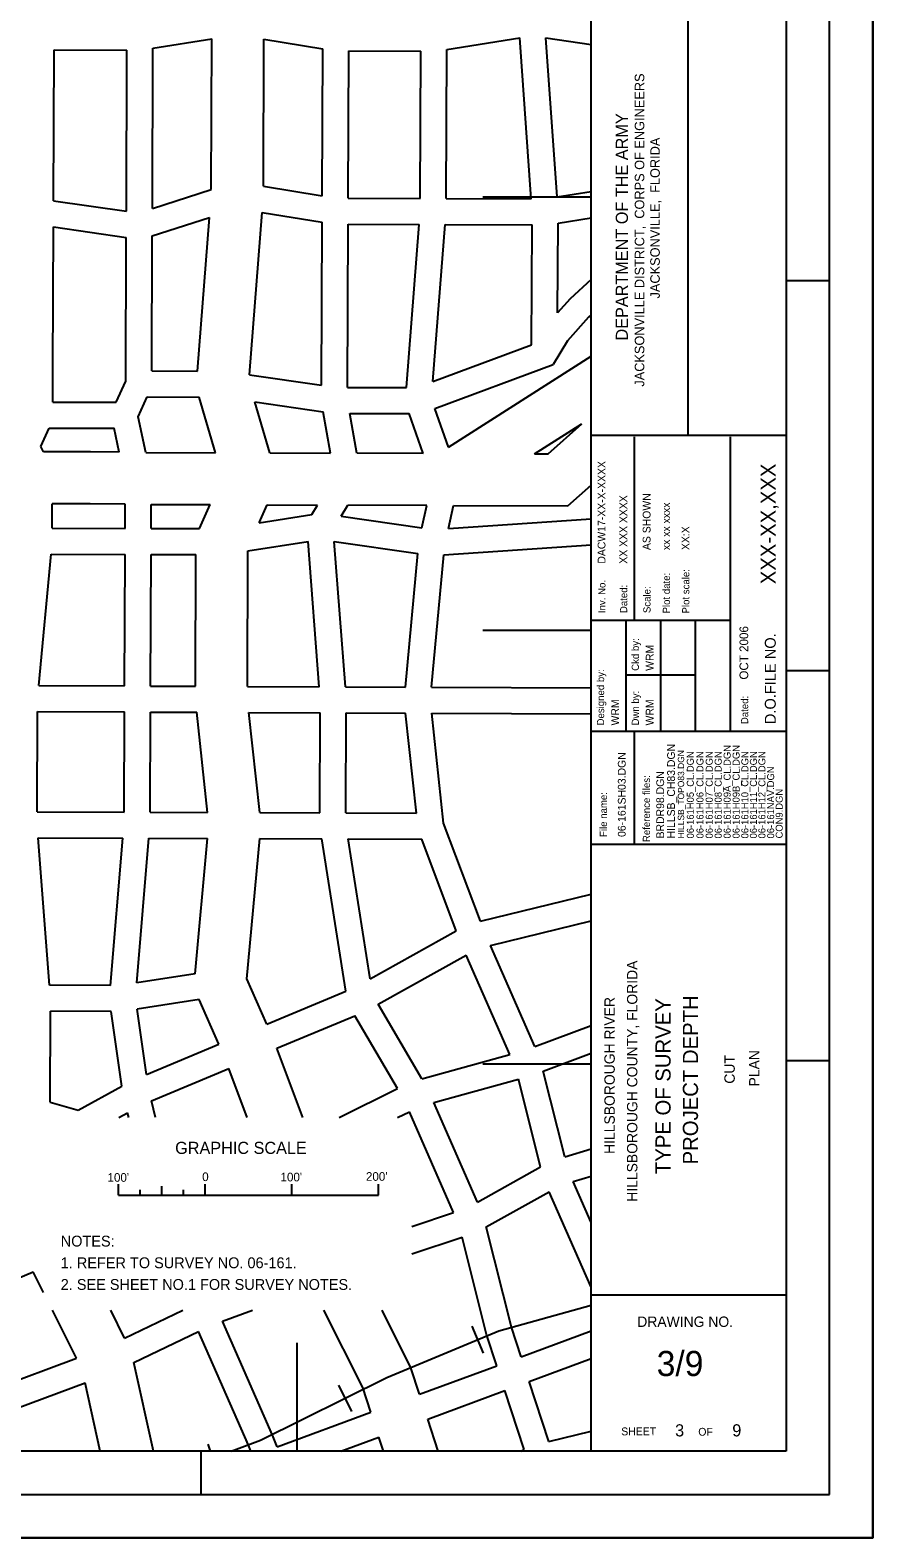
# Model space of a CAD drawing. Extents: x 501128 to 509328, y 1314906 to 1320706.
# Drawn here: x 507384 to 509328, y 1314906 to 1318384 of the extents above; entities that cross this region are included whole.
import ezdxf

# ---------------------------------------------------------------- set-up
doc = ezdxf.new("R2010")
doc.units = 0
for name, color, linetype in [('G-ANNO-TEXT', 7, 'Continuous'), ('G-ANNO-TTLB', 7, 'Continuous'), ('Level 1', 7, 'Continuous'), ('Level 14', 7, 'Continuous'), ('Level 2', 7, 'Continuous'), ('Level 32', 7, 'Continuous'), ('Level 37', 7, 'Continuous'), ('Level 5', 7, 'Continuous'), ('Level 6', 7, 'Continuous')]:
    doc.layers.add(name, color=color, linetype=linetype)

msp = doc.modelspace()

# ---------------------------------------------------------------- linework, layer by layer
at = {"layer": 'G-ANNO-TTLB'}
for p, q in [((509228.1, 1315006.3), (509228.1, 1320606.3)), ((508678.1, 1315106.3), (508678.1, 1320506.3)), ((509128.1, 1320506.3), (509128.1, 1315106.3)), ((508901.5, 1318488.9), (508901.5, 1317449.1)), ((509228.1, 1317806.3), (509128.1, 1317806.3)), ((509128.1, 1317449.1), (508678.1, 1317449.1)), ((508777.7, 1317446.3), (508777.7, 1317022.5)), ((508998.5, 1317446.3), (508998.5, 1316766.3)), ((508998.5, 1317022.5), (508678.1, 1317022.5)), ((508758.3, 1317022.5), (508758.3, 1316766.3)), ((508838.1, 1317022.5), (508838.1, 1316766.3)), ((508918.5, 1317022.5), (508918.5, 1316766.3)), ((508918.5, 1316896.7), (508758.3, 1316896.7)), ((509228.1, 1316906.3), (509128.1, 1316906.3)), ((509128.1, 1316766.3), (508678.1, 1316766.3)), ((508777.7, 1316766.3), (508777.7, 1316506.1)), ((509128.1, 1316506.1), (508678.1, 1316506.1)), ((509228.1, 1316006.3), (509128.1, 1316006.3)), ((509128.1, 1315466.3), (508678.1, 1315466.3)), ((509128.1, 1315106.3), (501478.1, 1315106.3)), ((507778.1, 1315006.3), (507778.1, 1315106.3)), ((501228.1, 1315006.3), (509228.1, 1315006.3))]:
    msp.add_line(p, q, dxfattribs=at)
for points in [[(501128.1, 1314906.3), (509328.1, 1314906.3), (509328.1, 1320706.3), (501128.1, 1320706.3)], [(501128.1, 1314906.3), (509328.1, 1314906.3), (509328.1, 1320706.3), (501128.1, 1320706.3)], [(501128.1, 1320706.3), (509328.1, 1320706.3), (509328.1, 1314906.3), (501128.1, 1314906.3)]]:
    msp.add_lwpolyline(points, close=True, dxfattribs=at)
msp.add_lwpolyline([(509278.1, 1314906.3), (509328.1, 1314906.3), (509328.1, 1314956.3)], dxfattribs=at)
at = {"layer": 'Level 1'}
for p, q in [((507587.2, 1315697.1), (507587.2, 1315722.2)), ((507687.2, 1315697.1), (507687.2, 1315717.6)), ((507787.2, 1315697.1), (507787.2, 1315722.2)), ((507787.2, 1315697.1), (507787.2, 1315722.2)), ((507987.2, 1315697.1), (507987.2, 1315722.2)), ((508187.2, 1315697.1), (508187.2, 1315722.2)), ((507587.2, 1315697.1), (508187.3, 1315697.1)), ((507637.2, 1315697.6), (507637.2, 1315709.1)), ((507687.2, 1315697.6), (507687.2, 1315709.1)), ((507737.2, 1315697.6), (507737.2, 1315709.1)), ((507787.2, 1315697.1), (507787.2, 1315709.1))]:
    msp.add_line(p, q, dxfattribs=at)
at = {"layer": 'Level 14'}
for p, q in [((507801.6, 1318016.3), (507803, 1318363.9)), ((507921.7, 1318024.3), (507922.9, 1318363.5)), ((507437.3, 1317990.9), (507438.6, 1318339)), ((507769.8, 1317597.9), (507797.4, 1317952)), ((507889.5, 1317589.1), (507918.7, 1317964)), ((507435.9, 1317605.5), (507437.1, 1317930.3)), ((508348.9, 1317422.4), (508678.1, 1317632.5)), ((507435.6, 1317526.4), (507435.9, 1317605.5)), ((507811.3, 1317409.6), (507773.9, 1317537.9)), ((507936.5, 1317409.1), (507902.2, 1317526.6)), ((507408.5, 1317423.8), (507427.7, 1317466.5)), ((508547.7, 1317406.9), (508656.9, 1317476.5)), ((507414.1, 1317411.3), (507408.5, 1317423.8)), ((507650.8, 1317410.2), (507811.3, 1317409.6)), ((507936.5, 1317409.1), (508076.5, 1317408.6)), ((508290.5, 1317407.8), (508137.4, 1317408.4)), ((507434.5, 1317235.6), (507434.7, 1317291.3)), ((507662.9, 1317290.2), (507798.9, 1317289.7)), ((507774.1, 1317234.3), (507798.9, 1317289.7)), ((507911.7, 1317247.9), (507930.2, 1317289.2)), ((507930.2, 1317289.2), (508046.8, 1317288.7)), ((508299.1, 1317287.8), (508116.5, 1317288.5)), ((507403.7, 1316872.2), (507431.8, 1317175.6)), ((507765.1, 1316870.8), (507766.2, 1317174.4)), ((507885.1, 1316870.4), (507886.2, 1317183.2)), ((507399.7, 1316581.3), (507400.6, 1316812.2)), ((507792.5, 1316579.9), (507767.8, 1316810.8)), ((507913.3, 1316579.4), (507888.5, 1316810.3)), ((507428.3, 1316181.3), (507402.1, 1316521.3)), ((507764.2, 1316207.4), (507793.1, 1316519.9)), ((507883.7, 1316196.1), (507913.6, 1316519.4)), ((507929.8, 1316091.1), (507883.7, 1316196.1)), ((507819.1, 1316044.9), (507773.7, 1316148.2)), ((507429.5, 1315911.1), (507430.3, 1316121.3)), ((508012.6, 1315875.7), (507952.5, 1316035.6)), ((507884.4, 1315875.7), (507841.7, 1315989.3)), ((507414.6, 1315472.1), (507390.8, 1315519.6)), ((507490.8, 1315320.6), (507435.1, 1315431.3)), ((507601.6, 1315367.3), (507569.4, 1315431.3)), ((508150.9, 1315252.9), (508061.2, 1315431.3)), ((508262.1, 1315298.8), (508195.5, 1315431.3)), ((507667.8, 1315106.3), (507623.1, 1315311.1)), ((508282.2, 1315237.4), (508262.1, 1315298.8)), ((507544.9, 1315106.3), (507510.6, 1315264)), ((508169.5, 1315195.9), (508150.9, 1315252.9)), ((508325.3, 1315106.3), (508300.9, 1315180.4)), ((508199, 1315106.3), (508188.3, 1315138.8))]:
    msp.add_line(p, q, dxfattribs=at)
for points in [[(508547.7, 1317406.9), (508578.8, 1317406.7), (508656.9, 1317476.5)], [(507589.3, 1317410.7), (507522.5, 1317411.3), (507414.1, 1317411.3)], [(508360.6, 1317287.6), (508624.5, 1317286.6), (508678.1, 1317334.6)], [(507602.9, 1317290.5), (507522, 1317291.3), (507434.7, 1317291.3)]]:
    msp.add_lwpolyline(points, dxfattribs=at)
at = {"layer": 'Level 2'}
for p, q in [((508428.1, 1318000), (508678.1, 1318000)), ((508428.1, 1317000), (508678.1, 1317000)), ((508428.1, 1316000), (508678.1, 1316000)), ((508000, 1315106.3), (508000, 1315356.3))]:
    msp.add_line(p, q, dxfattribs=at)
at = {"layer": 'Level 32'}
for p, q in [((507666.9, 1318342.6), (507803, 1318363.9)), ((507922.9, 1318363.5), (508058.8, 1318341.1)), ((508344.8, 1318340), (508513.4, 1318366.5)), ((508539.5, 1317994.9), (508513.4, 1318366.5)), ((508599.3, 1317999.5), (508573.6, 1318366.2)), ((508573.6, 1318366.2), (508678.1, 1318351.1)), ((507438.6, 1318339), (507606.9, 1318338.3)), ((507605.5, 1317966.6), (507606.9, 1318338.3)), ((507665.5, 1317973), (507666.9, 1318342.6)), ((508057.6, 1318001.9), (508058.8, 1318341.1)), ((508117.5, 1317996.5), (508118.8, 1318336.4)), ((508118.8, 1318336.4), (508284.8, 1318335.8)), ((508283.5, 1317995.9), (508284.8, 1318335.8)), ((508343.5, 1317995.7), (508344.8, 1318340)), ((507665.5, 1317973), (507801.6, 1318016.3)), ((507921.7, 1318024.3), (508057.6, 1318001.9)), ((508599.3, 1317999.5), (508678.1, 1318011.9)), ((507437.3, 1317990.9), (507605.5, 1317966.6)), ((508117.5, 1317996.5), (508283.5, 1317995.9)), ((508343.5, 1317995.7), (508539.5, 1317994.9)), ((507665.3, 1317910), (507797.4, 1317952)), ((507918.7, 1317964), (508057.3, 1317941.2)), ((508055.9, 1317565), (508057.3, 1317941.2)), ((508601.6, 1317939.1), (508678.1, 1317951.2)), ((507437.1, 1317930.3), (507605.2, 1317906)), ((507604, 1317574.9), (507605.2, 1317906)), ((507664.1, 1317598.3), (507665.3, 1317910)), ((508115.9, 1317560.3), (508117.3, 1317936.5)), ((508117.3, 1317936.5), (508281, 1317935.9)), ((508251.7, 1317559.7), (508281, 1317935.9)), ((508313, 1317574.1), (508341.2, 1317935.7)), ((508341.2, 1317935.7), (508541.6, 1317934.9)), ((508540.5, 1317658.5), (508541.6, 1317934.9)), ((508600.8, 1317732.5), (508601.6, 1317939.1)), ((508313, 1317574.1), (508540.5, 1317658.5)), ((507664.1, 1317598.3), (507769.8, 1317597.9)), ((508317.6, 1317511.8), (508590.8, 1317613.2)), ((507582, 1317525.9), (507604, 1317574.9)), ((507889.5, 1317589.1), (508055.9, 1317565)), ((508115.9, 1317560.3), (508251.7, 1317559.7)), ((507435.6, 1317526.4), (507582, 1317525.9)), ((507632.8, 1317492.6), (507653.4, 1317538.3)), ((507653.4, 1317538.3), (507773.9, 1317537.9)), ((507902.2, 1317526.6), (508060, 1317503.8)), ((507650.8, 1317410.2), (507632.8, 1317492.6)), ((508076.5, 1317408.6), (508060, 1317503.8)), ((508137.4, 1317408.4), (508121.5, 1317500.2)), ((508121.5, 1317500.2), (508258.2, 1317499.7)), ((508290.5, 1317407.8), (508258.2, 1317499.7)), ((508348.9, 1317422.4), (508317.6, 1317511.8)), ((507427.7, 1317466.5), (507577.2, 1317465.9)), ((507589.3, 1317410.7), (507577.2, 1317465.9)), ((507602.7, 1317235), (507602.9, 1317290.5)), ((507662.7, 1317234.8), (507662.9, 1317290.2)), ((508033.9, 1317267.1), (508046.8, 1317288.7)), ((508101.2, 1317262.9), (508116.5, 1317288.5)), ((508287.4, 1317236), (508299.1, 1317287.8)), ((508348.7, 1317234.9), (508360.6, 1317287.6)), ((507911.7, 1317247.9), (508033.9, 1317267.1)), ((508101.2, 1317262.9), (508287.4, 1317236)), ((508348.7, 1317234.9), (508678.1, 1317256.9)), ((507434.5, 1317235.6), (507602.7, 1317235)), ((507662.7, 1317234.8), (507774.1, 1317234.3)), ((507431.8, 1317175.6), (507602.5, 1317175)), ((507601.4, 1316871.4), (507602.5, 1317175)), ((507661.4, 1316871.2), (507662.5, 1317174.8)), ((507662.5, 1317174.8), (507766.2, 1317174.4)), ((507886.2, 1317183.2), (508025, 1317205)), ((508050.8, 1316869.7), (508025, 1317205)), ((508111, 1316869.5), (508085.2, 1317204.6)), ((508085.2, 1317204.6), (508278.1, 1317176.7)), ((508249.6, 1316869), (508278.1, 1317176.7)), ((508338.1, 1317174.1), (508678.1, 1317196.8)), ((508309.8, 1316868.8), (508338.1, 1317174.1)), ((507403.7, 1316872.2), (507601.4, 1316871.4)), ((507661.4, 1316871.2), (507765.1, 1316870.8)), ((507885.1, 1316870.4), (508050.8, 1316869.7)), ((508111, 1316869.5), (508249.6, 1316869)), ((508309.8, 1316868.8), (508678.1, 1316867.4)), ((507400.6, 1316812.2), (507601.1, 1316811.4)), ((507600.3, 1316580.6), (507601.1, 1316811.4)), ((507660.3, 1316580.4), (507661.1, 1316811.2)), ((507661.1, 1316811.2), (507767.8, 1316810.8)), ((507888.5, 1316810.3), (508053.1, 1316809.7)), ((508052.2, 1316578.9), (508053.1, 1316809.7)), ((508112.2, 1316578.7), (508113.1, 1316809.5)), ((508113.1, 1316809.5), (508249.9, 1316809)), ((508274.7, 1316578.1), (508249.9, 1316809)), ((508337.5, 1316554.9), (508310.3, 1316808.8)), ((508310.3, 1316808.8), (508678.1, 1316807.4)), ((507399.7, 1316581.3), (507600.3, 1316580.6)), ((507660.3, 1316580.4), (507792.5, 1316579.9)), ((507913.3, 1316579.4), (508052.2, 1316578.9)), ((508112.2, 1316578.7), (508274.7, 1316578.1)), ((508422.7, 1316328.6), (508337.5, 1316554.9)), ((507402.1, 1316521.3), (507597.5, 1316520.6)), ((507568.8, 1316180.8), (507597.5, 1316520.6)), ((507629.5, 1316186.3), (507657.7, 1316520.4)), ((507657.7, 1316520.4), (507793.1, 1316519.9)), ((507913.6, 1316519.4), (508056.5, 1316518.9)), ((508111.9, 1316167.2), (508056.5, 1316518.9)), ((508168.1, 1316195.8), (508117.2, 1316518.6)), ((508117.2, 1316518.6), (508287.3, 1316518)), ((508366.8, 1316306.7), (508287.3, 1316518)), ((508422.7, 1316328.6), (508678.1, 1316391.5)), ((508168.1, 1316195.8), (508366.8, 1316306.7)), ((508445.8, 1316272.5), (508678.1, 1316329.7)), ((508548.1, 1316039.7), (508445.8, 1316272.5)), ((508186.6, 1316137.4), (508389.8, 1316250.8)), ((508490.6, 1316021.4), (508389.8, 1316250.8)), ((507764.2, 1316207.4), (507629.5, 1316186.3)), ((507568.8, 1316180.8), (507428.3, 1316181.3)), ((507929.8, 1316091.1), (508111.9, 1316167.2)), ((507773.7, 1316148.2), (507630.3, 1316125.6)), ((508287.7, 1315965.1), (508186.6, 1316137.4)), ((507570.4, 1316120.8), (507430.3, 1316121.3)), ((507595.2, 1315948.6), (507570.4, 1316120.8)), ((507652, 1315975.1), (507630.3, 1316125.6)), ((507952.5, 1316035.6), (508132.6, 1316110.8)), ((508231.3, 1315942.6), (508132.6, 1316110.8)), ((508548.1, 1316039.7), (508678.1, 1316088)), ((507652, 1315975.1), (507819.1, 1316044.9)), ((508287.7, 1315965.1), (508490.6, 1316021.4)), ((508567.7, 1315983), (508678.1, 1316024)), ((507663.2, 1315914.7), (507841.7, 1315989.3)), ((508314.9, 1315910.4), (508510.4, 1315964.6)), ((508561, 1315762), (508510.4, 1315964.6)), ((508617.1, 1315784.9), (508567.7, 1315983)), ((507494.7, 1315892.5), (507595.2, 1315948.6)), ((508096.5, 1315875.7), (508231.3, 1315942.6)), ((507429.5, 1315911.1), (507494.7, 1315892.5)), ((507672.9, 1315875.7), (507663.2, 1315914.7)), ((508231.6, 1315875.7), (508258.7, 1315889.2)), ((508360.8, 1315656.7), (508258.7, 1315889.2)), ((508415.7, 1315681), (508314.9, 1315910.4)), ((507587.8, 1315875.7), (507608.2, 1315887.1)), ((507611.1, 1315875.7), (507608.2, 1315887.1)), ((508617.1, 1315784.9), (508678.1, 1315803.4)), ((508415.7, 1315681), (508561, 1315762)), ((508636.7, 1315728.1), (508678.1, 1315740.7)), ((508678.1, 1315633.9), (508636.7, 1315728.1)), ((508436.2, 1315623.7), (508581.5, 1315704.8)), ((508678.1, 1315484.8), (508581.5, 1315704.8)), ((508264.3, 1315624.5), (508360.8, 1315656.7)), ((508494, 1315392.3), (508436.2, 1315623.7)), ((508264.3, 1315561.3), (508380.3, 1315600)), ((508436.3, 1315375.6), (508380.3, 1315600)), ((507221.6, 1315448.9), (507390.8, 1315519.6)), ((507601.6, 1315367.3), (507735.5, 1315431.3)), ((507827.6, 1315405.8), (507896.4, 1315431.3)), ((507943.1, 1315142.9), (507827.6, 1315405.8)), ((507623.1, 1315311.1), (507772.3, 1315382.4)), ((507887.6, 1315120.2), (507772.3, 1315382.4)), ((508460.2, 1315303.1), (508436.3, 1315375.6)), ((508516.5, 1315323.9), (508494, 1315392.3)), ((508516.5, 1315323.9), (508678.1, 1315383.6)), ((507296.9, 1315248.7), (507490.8, 1315320.6)), ((508282.2, 1315237.4), (508460.2, 1315303.1)), ((508535.3, 1315266.9), (508678.1, 1315319.7)), ((507318, 1315192.5), (507510.6, 1315264)), ((508580.7, 1315128.5), (508535.3, 1315266.9)), ((508300.9, 1315180.4), (508478.9, 1315246.1)), ((508523.8, 1315109.8), (508478.9, 1315246.1)), ((507953.3, 1315116.1), (508169.5, 1315195.9)), ((507953.3, 1315116.1), (507943.1, 1315142.9)), ((508100.1, 1315106.3), (508188.3, 1315138.8)), ((508580.7, 1315128.5), (508678.1, 1315152.5)), ((507892.9, 1315106.3), (507887.6, 1315120.2)), ((508515.5, 1315106.3), (508523.8, 1315109.8))]:
    msp.add_line(p, q, dxfattribs=at)
for points in [[(508678.1, 1317809), (508629.6, 1317764.6), (508600.8, 1317732.5)], [(508678.1, 1317727.7), (508672.3, 1317722.4), (508623.3, 1317667.6), (508590.8, 1317613.2)]]:
    msp.add_lwpolyline(points, dxfattribs=at)
at = {"layer": 'Level 37'}
for p, q in [((508429.6, 1315332.6), (508403.7, 1315394.8)), ((508125.5, 1315198.1), (508095.6, 1315258.5)), ((507799.9, 1315106.3), (507794, 1315122.4))]:
    msp.add_line(p, q, dxfattribs=at)
msp.add_lwpolyline([(507847.4, 1315106.3), (507915.4, 1315131.5), (508206.5, 1315275.9), (508465.2, 1315384), (508678.1, 1315443.1)], dxfattribs=at)

# ---------------------------------------------------------------- texts
at = {"layer": 'G-ANNO-TEXT'}
for s, height, rotation, p in [('JACKSONVILLE DISTRICT,  CORPS OF ENGINEERS', 21.998, 90, (508800.7, 1317561.9)), ('DEPARTMENT OF THE ARMY', 27.998, 90, (508762.9, 1317668.3)), ('JACKSONVILLE,  FLORIDA', 21.998, 90, (508836.5, 1317765.3)), ('Inv. No.', 16.6, 90, (508711.1, 1317039.5)), ('Plot date:', 16.6, 90, (508859.9, 1317038.7)), ('Plot scale: ', 16.6, 90, (508904.7, 1317038.7)), ('Dated:', 16.6, 90, (508761.3, 1317039.5)), ('Scale:', 16.6, 90, (508815.1, 1317039.5)), ('Ckd by:', 16.6, 90, (508788.3, 1316906.3)), ('D.O.FILE NO.', 25.2, 90, (509104.1, 1316783.3)), ('Designed by:', 16.6, 90, (508708.1, 1316780.3)), ('Dwn by:', 16.6, 90, (508788.3, 1316780.3)), ('Dated:', 16.6, 90, (509040.5, 1316783.3)), ('Reference files:', 16.6, 90.0009, (508813.9, 1316511.3)), ('File name:', 16.6, 90.0009, (508714.7, 1316523.1))]:
    msp.add_text(s, height=height, rotation=rotation, dxfattribs=at).set_placement(p)
msp.add_text('DRAWING NO.', height=24, dxfattribs=at).set_placement((508784.5, 1315392.9))
at = {"layer": 'Level 1'}
for s, height, p in [('GRAPHIC SCALE', 28, (507718.1, 1315791.9)), ('0', 20, (507780.6, 1315729.3)), ("100'", 20, (507961.3, 1315728.6)), ("200'", 20, (508158.4, 1315729.9)), ("100'", 20, (507562.1, 1315727.7)), ('NOTES:', 25, (507454.1, 1315578.3)), ('1. REFER TO SURVEY NO. 06-161.', 25, (507454.1, 1315528.3)), ('2. SEE SHEET NO.1 FOR SURVEY NOTES.', 25, (507454.1, 1315478.3))]:
    msp.add_text(s, height=height, dxfattribs=at).set_placement(p)
at = {"layer": 'Level 5'}
for s, height, rotation, p in [('AS SHOWN', 18, 90.0009, (508815.1, 1317184.9)), ('xx xx xxxx', 18, 90.0009, (508859.9, 1317184.9)), ('XX:X', 18, 90.0009, (508904.7, 1317184.9)), ('WRM', 18, 90.001, (508822.1, 1316906.3)), ('WRM', 18, 90.001, (508742.3, 1316780.3)), ('WRM', 18, 90.001, (508822.1, 1316780.3)), ('HILLSB_CH83.DGN', 18, 90.0009, (508871.5, 1316519.7)), ('06-161H09A_CL.DGN', 16.2, 90.0009, (509000, 1316519.7)), ('06-161H09B_CL.DGN', 16.2, 90.0009, (509020.7, 1316519.7)), ('06-161SH03.DGN', 18, 90.0009, (508757.7, 1316523.1)), ('HILLSB_TOPO83.DGN', 14.58, 90.0009, (508892.7, 1316519.7)), ('06-161H05_CL.DGN', 16.2, 90.0009, (508915, 1316519.7)), ('06-161H06_CL.DGN', 16.2, 90.0009, (508937.3, 1316519.7)), ('06-161H07_CL.DGN', 16.2, 90.0009, (508958.6, 1316519.7)), ('06-161H08_CL.DGN', 16.2, 90.0009, (508979.3, 1316519.7)), ('06-161H10_CL.DGN', 16.2, 90.0009, (509040.9, 1316519.7)), ('06-161H11_CL.DGN', 16.2, 90.0009, (509060.6, 1316519.7)), ('06-161H12_CL.DGN', 16.2, 90.0009, (509080.2, 1316519.7)), ('06-161NAV.DGN', 16.2, 90.0009, (509100.4, 1316519.7)), ('CON9.DGN', 16.2, 90.0009, (509120.1, 1316519.7)), ('SHEET', 18.1, 0.34, (508747.5, 1315142.7))]:
    msp.add_text(s, height=height, rotation=rotation, dxfattribs=at).set_placement(p)
for s, height, p in [('3/9', 58, (508829.3, 1315279.5)), ('3', 28, (508871.8, 1315140.3)), ('OF', 18.11, (508925.3, 1315141.9)), ('9', 28, (509003.8, 1315140.3))]:
    msp.add_text(s, height=height, dxfattribs=at).set_placement(p)
at = {"layer": 'Level 6'}
for s, height, rotation, p in [('DACW17-XX-X-XXXX', 17.999, 90.0009, (508711.1, 1317153.5)), ('XXX-XX,XXX', 35, 90, (509104.1, 1317106.1)), ('XX XXX XXXX', 17.999, 90.0009, (508761.3, 1317153.5)), ('OCT 2006', 20, 90, (509040.5, 1316886.1)), ('BRDR98.DGN', 18, 90.0009, (508846.4, 1316519.7)), ('HILLSBOROUGH COUNTY, FLORIDA', 24, 90, (508784.8, 1315681.6)), ('HILLSBOROUGH RIVER', 24, 90, (508732.6, 1315791.9)), ('TYPE OF SURVEY', 35, 90, (508861.5, 1315745.3)), ('PROJECT DEPTH', 35, 90, (508924.7, 1315767.7)), ('PLAN', 24, 90, (509066.5, 1315947.5)), ('CUT', 24, 90, (509009.5, 1315953.9))]:
    msp.add_text(s, height=height, rotation=rotation, dxfattribs=at).set_placement(p)

doc.saveas('drawing.dxf')
